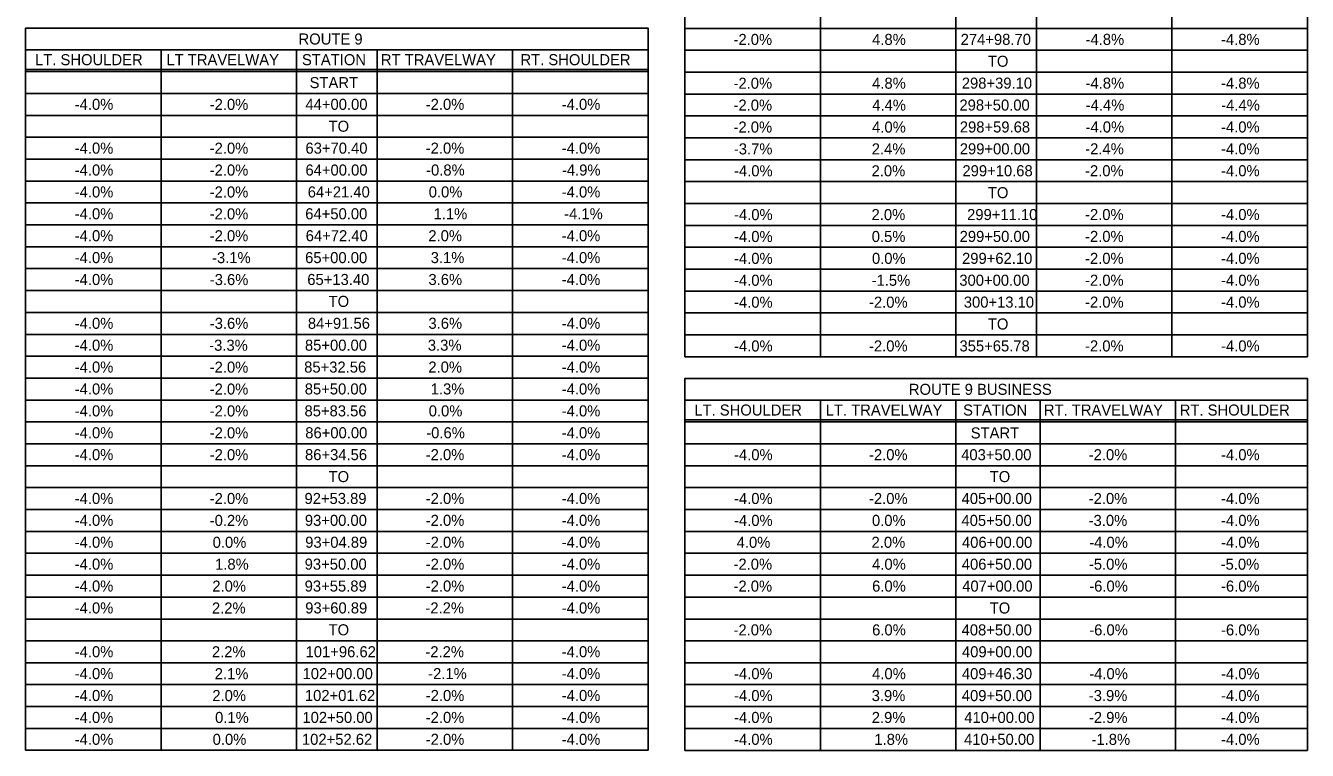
# Model space of a CAD drawing. Extents: x -15318841 to 1762012, y 465773 to 3693661.
# Drawn here: x -15310976.2 to -15310628.3, y 3690925.6 to 3691122.3 of the extents above; entities that cross this region are included whole.
import ezdxf

# ---------------------------------------------------------------- set-up
doc = ezdxf.new("R2010")
doc.units = 0
doc.layers.add('BORDER', color=7, linetype='Continuous')
doc.layers.add('DIMENSIONS', color=7, linetype='Continuous')

msp = doc.modelspace()

# ---------------------------------------------------------------- linework, layer by layer
at = {"layer": 'BORDER'}
for p, q in [((-15310760.51, 3691436.42), (-15310760.51, 3691032.38)), ((-15310723.75, 3691436.42), (-15310723.75, 3691032.38)), ((-15310701.87, 3691436.42), (-15310701.87, 3691032.38)), ((-15310665.1, 3691436.42), (-15310665.1, 3691032.38)), ((-15310797.28, 3691121.52), (-15310628.33, 3691121.52)), ((-15310939.46, 3691115.66), (-15310939.46, 3690925.61)), ((-15310902.69, 3691115.66), (-15310902.69, 3690925.61)), ((-15310880.82, 3691115.66), (-15310880.82, 3690925.61)), ((-15310844.05, 3691115.66), (-15310844.05, 3690925.61)), ((-15310797.28, 3691115.58), (-15310628.33, 3691115.58)), ((-15310976.23, 3691110.38), (-15310807.28, 3691110.38)), ((-15310976.23, 3691109.78), (-15310807.28, 3691109.78)), ((-15310797.28, 3691109.63), (-15310628.33, 3691109.63)), ((-15310976.23, 3691103.84), (-15310807.28, 3691103.84)), ((-15310976.23, 3691103.84), (-15310807.28, 3691103.84)), ((-15310976.23, 3691103.84), (-15310807.28, 3691103.84)), ((-15310797.28, 3691103.69), (-15310628.33, 3691103.69)), ((-15310976.23, 3691097.9), (-15310807.28, 3691097.9)), ((-15310797.28, 3691097.75), (-15310628.33, 3691097.75)), ((-15310976.23, 3691091.95), (-15310807.28, 3691091.95)), ((-15310797.28, 3691091.81), (-15310628.33, 3691091.81)), ((-15310976.23, 3691086.01), (-15310807.28, 3691086.01)), ((-15310797.28, 3691085.86), (-15310628.33, 3691085.86)), ((-15310976.23, 3691080.07), (-15310807.28, 3691080.07)), ((-15310797.28, 3691079.92), (-15310628.33, 3691079.92)), ((-15310976.23, 3691074.13), (-15310807.28, 3691074.13)), ((-15310797.28, 3691073.98), (-15310628.33, 3691073.98)), ((-15310976.23, 3691068.18), (-15310807.28, 3691068.18)), ((-15310797.28, 3691068.04), (-15310628.33, 3691068.04)), ((-15310976.23, 3691062.24), (-15310807.28, 3691062.24)), ((-15310797.28, 3691062.09), (-15310628.33, 3691062.09)), ((-15310976.23, 3691056.3), (-15310807.28, 3691056.3)), ((-15310797.28, 3691056.15), (-15310628.33, 3691056.15)), ((-15310976.23, 3691050.35), (-15310807.28, 3691050.35)), ((-15310797.28, 3691050.21), (-15310628.33, 3691050.21)), ((-15310976.23, 3691044.41), (-15310807.28, 3691044.41)), ((-15310797.28, 3691044.27), (-15310628.33, 3691044.27)), ((-15310976.23, 3691038.47), (-15310807.28, 3691038.47)), ((-15310797.28, 3691038.32), (-15310628.33, 3691038.32)), ((-15310976.23, 3691032.53), (-15310807.28, 3691032.53)), ((-15310976.23, 3691026.58), (-15310807.28, 3691026.58)), ((-15310976.23, 3691020.64), (-15310807.28, 3691020.64)), ((-15310760.51, 3691020.58), (-15310760.51, 3690925.56)), ((-15310723.75, 3691020.58), (-15310723.75, 3690925.56)), ((-15310700.87, 3691020.58), (-15310700.87, 3690925.56)), ((-15310664.1, 3691020.58), (-15310664.1, 3690925.56)), ((-15310664.1, 3691020.58), (-15310664.1, 3690925.56)), ((-15310976.23, 3691014.7), (-15310807.28, 3691014.7)), ((-15310797.28, 3691015.29), (-15310628.33, 3691015.29)), ((-15310797.28, 3691014.7), (-15310628.33, 3691014.7)), ((-15310976.23, 3691008.76), (-15310807.28, 3691008.76)), ((-15310797.28, 3691008.76), (-15310628.33, 3691008.76)), ((-15310797.28, 3691008.76), (-15310628.33, 3691008.76)), ((-15310797.28, 3691008.76), (-15310628.33, 3691008.76)), ((-15310976.23, 3691002.81), (-15310807.28, 3691002.81)), ((-15310797.28, 3691002.81), (-15310628.33, 3691002.81)), ((-15310976.23, 3690996.87), (-15310807.28, 3690996.87)), ((-15310797.28, 3690996.87), (-15310628.33, 3690996.87)), ((-15310976.23, 3690990.93), (-15310807.28, 3690990.93)), ((-15310797.28, 3690990.93), (-15310628.33, 3690990.93)), ((-15310976.23, 3690984.98), (-15310807.28, 3690984.98)), ((-15310797.28, 3690984.98), (-15310628.33, 3690984.98)), ((-15310976.23, 3690979.04), (-15310807.28, 3690979.04)), ((-15310797.28, 3690979.04), (-15310628.33, 3690979.04)), ((-15310976.23, 3690973.1), (-15310807.28, 3690973.1)), ((-15310797.28, 3690973.1), (-15310628.33, 3690973.1)), ((-15310976.23, 3690967.16), (-15310807.28, 3690967.16)), ((-15310797.28, 3690967.16), (-15310628.33, 3690967.16)), ((-15310976.23, 3690961.21), (-15310807.28, 3690961.21)), ((-15310797.28, 3690961.21), (-15310628.33, 3690961.21)), ((-15310976.23, 3690955.27), (-15310807.28, 3690955.27)), ((-15310797.28, 3690955.27), (-15310628.33, 3690955.27)), ((-15310976.23, 3690949.33), (-15310807.28, 3690949.33)), ((-15310797.28, 3690949.33), (-15310628.33, 3690949.33)), ((-15310976.23, 3690943.39), (-15310807.28, 3690943.39)), ((-15310797.28, 3690943.39), (-15310628.33, 3690943.39)), ((-15310976.23, 3690937.44), (-15310807.28, 3690937.44)), ((-15310797.28, 3690937.44), (-15310628.33, 3690937.44)), ((-15310976.23, 3690931.52), (-15310807.28, 3690931.52)), ((-15310797.28, 3690931.5), (-15310628.33, 3690931.5))]:
    msp.add_line(p, q, dxfattribs=at)
for points in [[(-15310797.28, 3691436.42), (-15310628.33, 3691436.42), (-15310628.33, 3691032.38), (-15310797.28, 3691032.38)], [(-15310976.23, 3691115.66), (-15310807.28, 3691115.66), (-15310807.28, 3690925.61), (-15310976.23, 3690925.61)], [(-15310797.28, 3691020.58), (-15310628.33, 3691020.58), (-15310628.33, 3690925.56), (-15310797.28, 3690925.56)]]:
    msp.add_lwpolyline(points, close=True, dxfattribs=at)
for points in [[(-15310976.23, 3691115.66), (-15310976.23, 3691121.6), (-15310807.28, 3691121.6), (-15310807.28, 3691115.66)], [(-15310797.28, 3691020.58), (-15310797.28, 3691026.52), (-15310628.33, 3691026.52), (-15310628.33, 3691020.58)]]:
    msp.add_lwpolyline(points, dxfattribs=at)

# ---------------------------------------------------------------- texts
at = {"layer": 'DIMENSIONS'}
for s, p in [('ROUTE 9', (-15310902.16, 3691117.13)), ('-2.0%', (-15310784.09, 3691117.02)), ('4.8%', (-15310746.47, 3691117.02)), ('274+98.70', (-15310722.44, 3691117.03)), ('-4.8%', (-15310688.54, 3691117.03)), ('-4.8%', (-15310651.77, 3691117.03)), ('LT. SHOULDER', (-15310973.67, 3691111.52)), ('LT TRAVELWAY', (-15310938.01, 3691111.52)), ('STATION', (-15310901.23, 3691111.52)), ('RT TRAVELWAY', (-15310879.8, 3691111.52)), ('RT. SHOULDER', (-15310841.92, 3691111.52)), ('TO', (-15310715.05, 3691111.09)), ('START', (-15310899.15, 3691105.29)), ('-2.0%', (-15310784.09, 3691105.13)), ('4.8%', (-15310746.47, 3691105.13)), ('298+39.10', (-15310722.13, 3691105.15)), ('-4.8%', (-15310688.54, 3691105.15)), ('-4.8%', (-15310651.77, 3691105.15)), ('-4.0%', (-15310962.9, 3691099.4)), ('-2.0%', (-15310926.27, 3691099.38)), ('44+00.00', (-15310900.28, 3691099.4)), ('-2.0%', (-15310867.63, 3691099.4)), ('-4.0%', (-15310830.72, 3691099.4)), ('-2.0%', (-15310784.09, 3691099.19)), ('4.4%', (-15310746.43, 3691099.19)), ('298+50.00', (-15310722.77, 3691099.2)), ('-4.4%', (-15310688.49, 3691099.2)), ('-4.4%', (-15310651.72, 3691099.2)), ('TO', (-15310894, 3691093.46)), ('-2.0%', (-15310784.09, 3691093.24)), ('4.0%', (-15310746.47, 3691093.24)), ('298+59.68', (-15310722.67, 3691093.26)), ('-4.0%', (-15310688.54, 3691093.26)), ('-4.0%', (-15310651.77, 3691093.26)), ('-4.0%', (-15310962.9, 3691087.51)), ('-2.0%', (-15310926.27, 3691087.5)), ('63+70.40', (-15310900.28, 3691087.51)), ('-2.0%', (-15310867.63, 3691087.51)), ('-4.0%', (-15310830.72, 3691087.51)), ('-3.7%', (-15310784, 3691087.3)), ('2.4%', (-15310746.57, 3691087.3)), ('299+00.00', (-15310722.68, 3691087.32)), ('-2.4%', (-15310688.63, 3691087.32)), ('-4.0%', (-15310651.77, 3691087.32)), ('-4.0%', (-15310962.9, 3691081.57)), ('-2.0%', (-15310926.27, 3691081.56)), ('64+00.00', (-15310900.28, 3691081.57)), ('-0.8%', (-15310867.53, 3691081.57)), ('-4.9%', (-15310830.67, 3691081.57)), ('-4.0%', (-15310783.95, 3691081.36)), ('2.0%', (-15310746.62, 3691081.36)), ('299+10.68', (-15310721.96, 3691081.38)), ('-2.0%', (-15310688.68, 3691081.38)), ('-4.0%', (-15310651.77, 3691081.38)), ('-4.0%', (-15310962.9, 3691075.63)), ('-2.0%', (-15310926.27, 3691075.61)), ('64+21.40', (-15310899.66, 3691075.63)), ('0.0%', (-15310866.82, 3691075.63)), ('-4.0%', (-15310830.72, 3691075.63)), ('TO', (-15310715.05, 3691075.43)), ('-4.0%', (-15310962.9, 3691069.69)), ('-2.0%', (-15310926.27, 3691069.67)), ('64+50.00', (-15310900.33, 3691069.69)), ('1.1%', (-15310865.5, 3691069.69)), ('-4.1%', (-15310830.06, 3691069.69)), ('-4.0%', (-15310783.95, 3691069.47)), ('2.0%', (-15310746.62, 3691069.47)), ('299+11.10', (-15310720.69, 3691069.49)), ('-2.0%', (-15310688.68, 3691069.49)), ('-4.0%', (-15310651.77, 3691069.49)), ('-4.0%', (-15310962.9, 3691063.74)), ('-2.0%', (-15310926.27, 3691063.73)), ('64+72.40', (-15310900.21, 3691063.74)), ('2.0%', (-15310866.92, 3691063.74)), ('-4.0%', (-15310830.72, 3691063.74)), ('-4.0%', (-15310783.95, 3691063.53)), ('0.5%', (-15310746.57, 3691063.53)), ('299+50.00', (-15310722.72, 3691063.55)), ('-2.0%', (-15310688.68, 3691063.55)), ('-4.0%', (-15310651.77, 3691063.55)), ('-4.0%', (-15310962.9, 3691057.8)), ('-3.1%', (-15310925.63, 3691057.79)), ('65+00.00', (-15310900.37, 3691057.8)), ('3.1%', (-15310866.28, 3691057.8)), ('-4.0%', (-15310830.72, 3691057.8)), ('-4.0%', (-15310783.95, 3691057.59)), ('0.0%', (-15310746.52, 3691057.59)), ('299+62.10', (-15310722.06, 3691057.6)), ('-2.0%', (-15310688.68, 3691057.6)), ('-4.0%', (-15310651.77, 3691057.6)), ('-4.0%', (-15310962.9, 3691051.86)), ('-3.6%', (-15310926.25, 3691051.84)), ('65+13.40', (-15310899.78, 3691051.86)), ('3.6%', (-15310866.9, 3691051.86)), ('-4.0%', (-15310830.72, 3691051.86)), ('-4.0%', (-15310783.95, 3691051.65)), ('-1.5%', (-15310746.61, 3691051.65)), ('300+00.00', (-15310722.8, 3691051.66)), ('-2.0%', (-15310688.68, 3691051.66)), ('-4.0%', (-15310651.77, 3691051.66)), ('TO', (-15310894, 3691045.92)), ('-4.0%', (-15310783.95, 3691045.7)), ('-2.0%', (-15310747.32, 3691045.7)), ('300+13.10', (-15310721.59, 3691045.72)), ('-2.0%', (-15310688.68, 3691045.72)), ('-4.0%', (-15310651.77, 3691045.72)), ('-4.0%', (-15310962.9, 3691039.97)), ('-3.6%', (-15310926.25, 3691039.96)), ('84+91.56', (-15310899.62, 3691039.97)), ('3.6%', (-15310866.9, 3691039.97)), ('-4.0%', (-15310830.72, 3691039.97)), ('TO', (-15310715.05, 3691039.78)), ('-4.0%', (-15310962.9, 3691034.03)), ('-3.3%', (-15310926.41, 3691034.01)), ('85+00.00', (-15310900.42, 3691034.03)), ('3.3%', (-15310867.06, 3691034.03)), ('-4.0%', (-15310830.72, 3691034.03)), ('-4.0%', (-15310783.95, 3691033.82)), ('-2.0%', (-15310747.32, 3691033.82)), ('355+65.78', (-15310722.76, 3691033.83)), ('-2.0%', (-15310688.68, 3691033.83)), ('-4.0%', (-15310651.77, 3691033.83)), ('-4.0%', (-15310962.9, 3691028.09)), ('-2.0%', (-15310926.27, 3691028.07)), ('85+32.56', (-15310900.63, 3691028.09)), ('2.0%', (-15310866.92, 3691028.09)), ('-4.0%', (-15310830.72, 3691028.09)), ('-4.0%', (-15310962.9, 3691022.15)), ('-2.0%', (-15310926.27, 3691022.13)), ('85+50.00', (-15310900.47, 3691022.15)), ('1.3%', (-15310866.28, 3691022.15)), ('-4.0%', (-15310830.72, 3691022.15)), ('ROUTE 9 BUSINESS', (-15310736.5, 3691022.05)), ('-4.0%', (-15310962.9, 3691016.2)), ('-2.0%', (-15310926.27, 3691016.19)), ('85+83.56', (-15310900.54, 3691016.2)), ('0.0%', (-15310866.82, 3691016.2)), ('-4.0%', (-15310830.72, 3691016.2)), ('LT. SHOULDER', (-15310794.73, 3691016.43)), ('LT. TRAVELWAY', (-15310759.06, 3691016.43)), ('STATION', (-15310721.78, 3691016.43)), ('RT. TRAVELWAY', (-15310699.85, 3691016.43)), ('RT. SHOULDER', (-15310662.98, 3691016.43)), ('-4.0%', (-15310962.9, 3691010.26)), ('-2.0%', (-15310926.27, 3691010.24)), ('86+00.00', (-15310900.33, 3691010.26)), ('-0.6%', (-15310867.49, 3691010.26)), ('-4.0%', (-15310830.72, 3691010.26)), ('START', (-15310719.71, 3691010.21)), ('-4.0%', (-15310962.9, 3691004.32)), ('-2.0%', (-15310926.27, 3691004.3)), ('86+34.56', (-15310900.4, 3691004.32)), ('-2.0%', (-15310867.63, 3691004.32)), ('-4.0%', (-15310830.72, 3691004.32)), ('-4.0%', (-15310783.95, 3691004.3)), ('-2.0%', (-15310747.32, 3691004.3)), ('403+50.00', (-15310722.3, 3691004.3)), ('-2.0%', (-15310687.68, 3691004.3)), ('-4.0%', (-15310651.77, 3691004.3)), ('TO', (-15310894, 3690998.37)), ('TO', (-15310714.55, 3690998.36)), ('-4.0%', (-15310962.9, 3690992.43)), ('-2.0%', (-15310926.27, 3690992.42)), ('92+53.89', (-15310900.54, 3690992.43)), ('-2.0%', (-15310867.63, 3690992.43)), ('-4.0%', (-15310830.72, 3690992.43)), ('-4.0%', (-15310783.95, 3690992.42)), ('-2.0%', (-15310747.32, 3690992.42)), ('405+00.00', (-15310722.18, 3690992.42)), ('-2.0%', (-15310687.68, 3690992.42)), ('-4.0%', (-15310651.77, 3690992.42)), ('-4.0%', (-15310962.9, 3690986.49)), ('-0.2%', (-15310926.27, 3690986.47)), ('93+00.00', (-15310900.44, 3690986.49)), ('-2.0%', (-15310867.63, 3690986.49)), ('-4.0%', (-15310830.72, 3690986.49)), ('-4.0%', (-15310783.95, 3690986.47)), ('0.0%', (-15310746.52, 3690986.47)), ('405+50.00', (-15310722.22, 3690986.47)), ('-3.0%', (-15310687.7, 3690986.47)), ('-4.0%', (-15310651.77, 3690986.47)), ('-4.0%', (-15310962.9, 3690980.55)), ('0.0%', (-15310925.47, 3690980.53)), ('93+04.89', (-15310900.35, 3690980.55)), ('-2.0%', (-15310867.63, 3690980.55)), ('-4.0%', (-15310830.72, 3690980.55)), ('4.0%', (-15310783.24, 3690980.53)), ('2.0%', (-15310746.62, 3690980.53)), ('406+00.00', (-15310722.08, 3690980.53)), ('-4.0%', (-15310687.54, 3690980.53)), ('-4.0%', (-15310651.77, 3690980.53)), ('-4.0%', (-15310962.9, 3690974.6)), ('1.8%', (-15310924.81, 3690974.59)), ('93+50.00', (-15310900.49, 3690974.6)), ('-2.0%', (-15310867.63, 3690974.6)), ('-4.0%', (-15310830.72, 3690974.6)), ('-2.0%', (-15310784.09, 3690974.59)), ('4.0%', (-15310746.47, 3690974.59)), ('406+50.00', (-15310722.13, 3690974.59)), ('-5.0%', (-15310687.63, 3690974.59)), ('-5.0%', (-15310651.87, 3690974.59)), ('-4.0%', (-15310962.9, 3690968.66)), ('2.0%', (-15310925.56, 3690968.64)), ('93+55.89', (-15310900.49, 3690968.66)), ('-2.0%', (-15310867.63, 3690968.66)), ('-4.0%', (-15310830.72, 3690968.66)), ('-2.0%', (-15310784.09, 3690968.64)), ('6.0%', (-15310746.47, 3690968.64)), ('407+00.00', (-15310722.01, 3690968.64)), ('-6.0%', (-15310687.54, 3690968.64)), ('-6.0%', (-15310651.77, 3690968.64)), ('-4.0%', (-15310962.9, 3690962.72)), ('2.2%', (-15310925.66, 3690962.7)), ('93+60.89', (-15310900.35, 3690962.72)), ('-2.2%', (-15310867.72, 3690962.72)), ('-4.0%', (-15310830.72, 3690962.72)), ('TO', (-15310714.55, 3690962.7)), ('TO', (-15310894, 3690956.78)), ('-2.0%', (-15310784.09, 3690956.76)), ('6.0%', (-15310746.47, 3690956.76)), ('408+50.00', (-15310722.18, 3690956.76)), ('-6.0%', (-15310687.54, 3690956.76)), ('-6.0%', (-15310651.77, 3690956.76)), ('-4.0%', (-15310962.9, 3690950.83)), ('101+96.62', (-15310900.24, 3690950.83)), ('-2.2%', (-15310867.72, 3690950.83)), ('-4.0%', (-15310830.72, 3690950.83)), ('2.2%', (-15310925.66, 3690950.82)), ('409+00.00', (-15310722.08, 3690950.82)), ('-4.0%', (-15310962.9, 3690944.89)), ('2.1%', (-15310924.9, 3690944.87)), ('102+00.00', (-15310901.06, 3690944.89)), ('-2.1%', (-15310866.97, 3690944.89)), ('-4.0%', (-15310830.72, 3690944.89)), ('-4.0%', (-15310783.95, 3690944.87)), ('4.0%', (-15310746.47, 3690944.87)), ('409+46.30', (-15310722.11, 3690944.87)), ('-4.0%', (-15310687.54, 3690944.87)), ('-4.0%', (-15310651.77, 3690944.87)), ('-4.0%', (-15310962.9, 3690938.95)), ('2.0%', (-15310925.56, 3690938.93)), ('102+01.62', (-15310900.43, 3690938.95)), ('-2.0%', (-15310867.63, 3690938.95)), ('-4.0%', (-15310830.72, 3690938.95)), ('-4.0%', (-15310783.95, 3690938.93)), ('3.9%', (-15310746.59, 3690938.93)), ('409+50.00', (-15310722.13, 3690938.93)), ('-3.9%', (-15310687.66, 3690938.93)), ('-4.0%', (-15310651.77, 3690938.93)), ('-4.0%', (-15310962.9, 3690933)), ('0.1%', (-15310924.81, 3690932.99)), ('102+50.00', (-15310901.1, 3690933)), ('-2.0%', (-15310867.63, 3690933)), ('-4.0%', (-15310830.72, 3690933)), ('-4.0%', (-15310783.95, 3690932.99)), ('2.9%', (-15310746.57, 3690932.99)), ('410+00.00', (-15310721.47, 3690932.99)), ('-2.9%', (-15310687.63, 3690932.99)), ('-4.0%', (-15310651.77, 3690932.99)), ('-4.0%', (-15310962.9, 3690927.06)), ('0.0%', (-15310925.47, 3690927.05)), ('102+52.62', (-15310901.23, 3690927.06)), ('-2.0%', (-15310867.63, 3690927.06)), ('-4.0%', (-15310830.72, 3690927.06)), ('-4.0%', (-15310783.95, 3690927.05)), ('1.8%', (-15310745.86, 3690927.05)), ('410+50.00', (-15310721.52, 3690927.05)), ('-1.8%', (-15310686.92, 3690927.05)), ('-4.0%', (-15310651.77, 3690927.05))]:
    msp.add_text(s, height=3, dxfattribs=at).set_placement(p)

doc.saveas('drawing.dxf')
